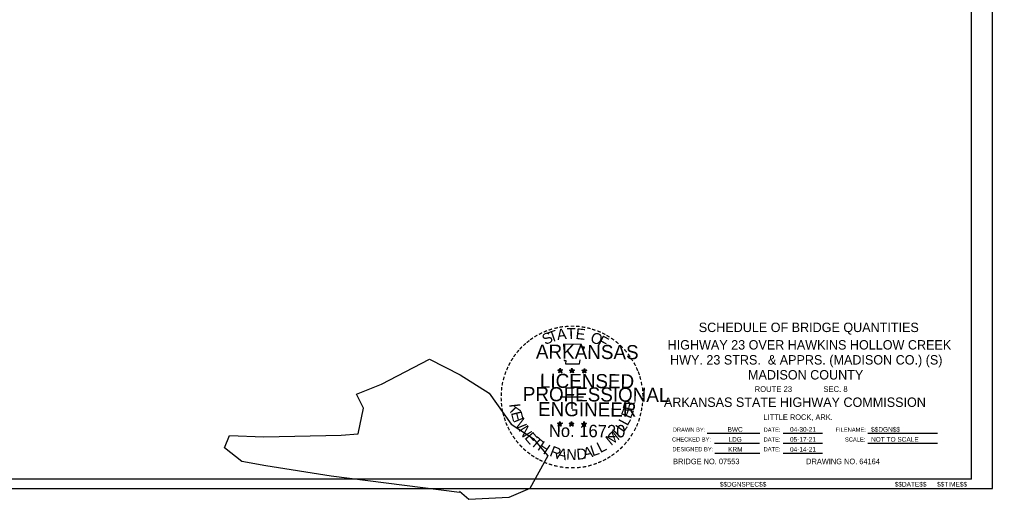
# Model space of a CAD drawing. Extents: x -1.3 to 32.1, y -0.4 to 20.7.
# Drawn here: x 11.36 to 32.07, y -0.43 to 9.78 of the extents above; entities that cross this region are included whole.
import ezdxf

# ---------------------------------------------------------------- set-up
doc = ezdxf.new("R2010")
doc.units = 0
for name, color, linetype in [('49B', 7, 'Continuous'), ('Level 1', 7, 'Continuous'), ('Level 4', 7, 'Continuous'), ('Level 48', 7, 'Continuous'), ('Level 63', 7, 'Continuous'), ('R_No Plot', 7, 'Continuous'), ('S_TREE', 7, 'Continuous')]:
    doc.layers.add(name, color=color, linetype=linetype)

msp = doc.modelspace()

# ---------------------------------------------------------------- linework, layer by layer
at = {"layer": '49B'}
for p, q in [((22.816, 2.325), (22.87, 2.308)), ((22.816, 2.325), (22.855, 2.323)), ((22.816, 2.325), (22.855, 2.321)), ((22.816, 2.325), (22.851, 2.315)), ((22.816, 2.325), (22.851, 2.31)), ((22.816, 2.325), (22.851, 2.308)), ((22.816, 2.325), (22.851, 2.302)), ((22.838, 2.263), (22.87, 2.308)), ((22.838, 2.263), (22.851, 2.306)), ((22.838, 2.263), (22.855, 2.3)), ((22.838, 2.263), (22.857, 2.299)), ((22.838, 2.263), (22.862, 2.295)), ((22.838, 2.263), (22.87, 2.295)), ((22.838, 2.263), (22.87, 2.291)), ((22.87, 2.365), (22.862, 2.325)), ((22.87, 2.365), (22.862, 2.328)), ((22.87, 2.365), (22.866, 2.328)), ((22.87, 2.308), (22.87, 2.365)), ((22.87, 2.365), (22.879, 2.325)), ((22.87, 2.365), (22.877, 2.328)), ((22.87, 2.365), (22.872, 2.328)), ((22.921, 2.325), (22.87, 2.308)), ((22.901, 2.262), (22.87, 2.308)), ((22.901, 2.262), (22.87, 2.295)), ((22.901, 2.262), (22.87, 2.291)), ((22.921, 2.325), (22.873, 2.321)), ((22.901, 2.262), (22.873, 2.295)), ((22.921, 2.325), (22.879, 2.317)), ((22.921, 2.325), (22.879, 2.313)), ((22.901, 2.262), (22.879, 2.306)), ((22.901, 2.262), (22.879, 2.3)), ((22.901, 2.262), (22.884, 2.308)), ((22.921, 2.325), (22.886, 2.313)), ((22.921, 2.325), (22.892, 2.31)), ((22.921, 2.325), (22.894, 2.308)), ((23.066, 2.323), (23.119, 2.308)), ((23.066, 2.323), (23.105, 2.321)), ((23.066, 2.323), (23.105, 2.317)), ((23.066, 2.323), (23.105, 2.315)), ((23.066, 2.323), (23.103, 2.308)), ((23.066, 2.323), (23.103, 2.306)), ((23.066, 2.323), (23.103, 2.3)), ((23.088, 2.262), (23.119, 2.308)), ((23.088, 2.262), (23.105, 2.302)), ((23.088, 2.262), (23.105, 2.3)), ((23.088, 2.262), (23.106, 2.299)), ((23.088, 2.262), (23.112, 2.293)), ((23.088, 2.262), (23.119, 2.293)), ((23.088, 2.262), (23.119, 2.291)), ((23.119, 2.362), (23.112, 2.323)), ((23.119, 2.362), (23.112, 2.325)), ((23.119, 2.362), (23.114, 2.325)), ((23.119, 2.308), (23.119, 2.362)), ((23.119, 2.362), (23.129, 2.323)), ((23.119, 2.362), (23.127, 2.325)), ((23.119, 2.362), (23.121, 2.325)), ((23.171, 2.323), (23.119, 2.308)), ((23.151, 2.262), (23.119, 2.308)), ((23.151, 2.262), (23.119, 2.293)), ((23.151, 2.262), (23.119, 2.291)), ((23.171, 2.323), (23.125, 2.321)), ((23.151, 2.262), (23.125, 2.293)), ((23.171, 2.323), (23.129, 2.315)), ((23.171, 2.323), (23.129, 2.313)), ((23.151, 2.262), (23.129, 2.306)), ((23.151, 2.262), (23.129, 2.299)), ((23.151, 2.262), (23.134, 2.306)), ((23.171, 2.323), (23.136, 2.31)), ((23.171, 2.323), (23.142, 2.308)), ((23.171, 2.323), (23.143, 2.306)), ((23.33, 2.321), (23.384, 2.302)), ((23.33, 2.321), (23.373, 2.315)), ((23.33, 2.321), (23.369, 2.313)), ((23.33, 2.321), (23.369, 2.31)), ((23.33, 2.321), (23.367, 2.306)), ((23.33, 2.321), (23.367, 2.3)), ((23.33, 2.321), (23.367, 2.3)), ((23.351, 2.26), (23.384, 2.302)), ((23.351, 2.26), (23.369, 2.3)), ((23.351, 2.26), (23.373, 2.295)), ((23.351, 2.26), (23.373, 2.293)), ((23.351, 2.26), (23.384, 2.293)), ((23.351, 2.26), (23.38, 2.291)), ((23.351, 2.26), (23.388, 2.286)), ((23.384, 2.358), (23.375, 2.323)), ((23.384, 2.358), (23.38, 2.321)), ((23.384, 2.358), (23.38, 2.321)), ((23.384, 2.302), (23.384, 2.358)), ((23.384, 2.358), (23.395, 2.321)), ((23.384, 2.358), (23.391, 2.321)), ((23.384, 2.358), (23.388, 2.321)), ((23.436, 2.321), (23.384, 2.302)), ((23.414, 2.26), (23.384, 2.302)), ((23.414, 2.26), (23.384, 2.293)), ((23.414, 2.26), (23.384, 2.286)), ((23.436, 2.321), (23.39, 2.315)), ((23.414, 2.26), (23.39, 2.291)), ((23.436, 2.321), (23.395, 2.313)), ((23.436, 2.321), (23.395, 2.308)), ((23.414, 2.26), (23.395, 2.3)), ((23.414, 2.26), (23.395, 2.295)), ((23.414, 2.26), (23.399, 2.3)), ((23.436, 2.321), (23.402, 2.306)), ((23.436, 2.321), (23.404, 2.306)), ((23.436, 2.321), (23.41, 2.302)), ((22.809, 1.189), (22.862, 1.172)), ((22.809, 1.189), (22.847, 1.187)), ((22.809, 1.189), (22.846, 1.181)), ((22.809, 1.189), (22.846, 1.181)), ((22.809, 1.189), (22.846, 1.174)), ((22.809, 1.189), (22.846, 1.172)), ((22.809, 1.189), (22.846, 1.17)), ((22.827, 1.131), (22.862, 1.172)), ((22.827, 1.131), (22.846, 1.172)), ((22.827, 1.131), (22.847, 1.165)), ((22.827, 1.131), (22.849, 1.165)), ((22.827, 1.131), (22.862, 1.163)), ((22.827, 1.131), (22.855, 1.159)), ((22.827, 1.131), (22.862, 1.157)), ((22.862, 1.229), (22.851, 1.192)), ((22.862, 1.229), (22.855, 1.189)), ((22.862, 1.229), (22.857, 1.189)), ((22.892, 1.128), (22.859, 1.157)), ((22.862, 1.172), (22.862, 1.229)), ((22.862, 1.229), (22.87, 1.189)), ((22.862, 1.229), (22.87, 1.189)), ((22.862, 1.229), (22.862, 1.189)), ((22.914, 1.189), (22.862, 1.172)), ((22.892, 1.128), (22.862, 1.172)), ((22.892, 1.128), (22.862, 1.159)), ((22.892, 1.128), (22.864, 1.159)), ((22.914, 1.189), (22.866, 1.187)), ((22.914, 1.189), (22.87, 1.181)), ((22.914, 1.189), (22.87, 1.179)), ((22.892, 1.128), (22.87, 1.172)), ((22.892, 1.128), (22.87, 1.165)), ((22.914, 1.189), (22.877, 1.178)), ((22.892, 1.128), (22.877, 1.172)), ((22.914, 1.189), (22.881, 1.174)), ((22.914, 1.189), (22.884, 1.172)), ((23.058, 1.189), (23.112, 1.172)), ((23.058, 1.189), (23.097, 1.185)), ((23.058, 1.189), (23.097, 1.181)), ((23.058, 1.189), (23.097, 1.179)), ((23.058, 1.189), (23.095, 1.174)), ((23.058, 1.189), (23.095, 1.17)), ((23.058, 1.189), (23.095, 1.166)), ((23.077, 1.128), (23.112, 1.172)), ((23.077, 1.128), (23.097, 1.17)), ((23.077, 1.128), (23.097, 1.163)), ((23.077, 1.128), (23.099, 1.163)), ((23.077, 1.128), (23.105, 1.159)), ((23.077, 1.128), (23.112, 1.159)), ((23.077, 1.128), (23.112, 1.155)), ((23.112, 1.226), (23.103, 1.189)), ((23.112, 1.226), (23.105, 1.189)), ((23.112, 1.226), (23.106, 1.189)), ((23.142, 1.128), (23.11, 1.155)), ((23.112, 1.172), (23.112, 1.226)), ((23.112, 1.226), (23.119, 1.187)), ((23.112, 1.226), (23.119, 1.187)), ((23.112, 1.226), (23.112, 1.189)), ((23.162, 1.187), (23.112, 1.172)), ((23.142, 1.128), (23.112, 1.172)), ((23.142, 1.128), (23.112, 1.159)), ((23.142, 1.128), (23.114, 1.159)), ((23.162, 1.187), (23.118, 1.187)), ((23.162, 1.187), (23.119, 1.179)), ((23.162, 1.187), (23.119, 1.179)), ((23.142, 1.128), (23.119, 1.17)), ((23.142, 1.128), (23.119, 1.165)), ((23.162, 1.187), (23.127, 1.174)), ((23.142, 1.128), (23.127, 1.17)), ((23.162, 1.187), (23.132, 1.172)), ((23.162, 1.187), (23.134, 1.17)), ((23.323, 1.185), (23.377, 1.166)), ((23.323, 1.185), (23.362, 1.181)), ((23.323, 1.185), (23.362, 1.178)), ((23.323, 1.185), (23.36, 1.174)), ((23.323, 1.185), (23.36, 1.17)), ((23.323, 1.185), (23.358, 1.166)), ((23.323, 1.185), (23.358, 1.163)), ((23.343, 1.124), (23.377, 1.166)), ((23.343, 1.124), (23.36, 1.166)), ((23.343, 1.124), (23.362, 1.159)), ((23.343, 1.124), (23.365, 1.159)), ((23.343, 1.124), (23.369, 1.155)), ((23.343, 1.124), (23.375, 1.155)), ((23.343, 1.124), (23.377, 1.152)), ((23.377, 1.224), (23.367, 1.185)), ((23.377, 1.224), (23.369, 1.185)), ((23.377, 1.224), (23.373, 1.185)), ((23.406, 1.124), (23.375, 1.155)), ((23.406, 1.124), (23.375, 1.152)), ((23.377, 1.166), (23.377, 1.224)), ((23.377, 1.224), (23.384, 1.185)), ((23.377, 1.224), (23.384, 1.185)), ((23.377, 1.224), (23.377, 1.185)), ((23.428, 1.185), (23.377, 1.166)), ((23.406, 1.124), (23.377, 1.166)), ((23.406, 1.124), (23.38, 1.155)), ((23.428, 1.185), (23.382, 1.181)), ((23.428, 1.185), (23.384, 1.178)), ((23.428, 1.185), (23.384, 1.174)), ((23.406, 1.124), (23.384, 1.159)), ((23.406, 1.124), (23.388, 1.166)), ((23.406, 1.124), (23.39, 1.166)), ((23.428, 1.185), (23.395, 1.172)), ((23.428, 1.185), (23.397, 1.166)), ((23.428, 1.185), (23.399, 1.166))]:
    msp.add_line(p, q, dxfattribs=at)
for points in [[(22.938, 2.872), (22.944, 2.757)], [(23.364, 2.757), (23.388, 2.809), (23.317, 2.809), (23.321, 2.868), (22.938, 2.872)], [(22.951, 2.543), (22.953, 2.528), (22.986, 2.526), (22.981, 2.458), (23.282, 2.456), (23.29, 2.543)], [(22.87, 2.365), (22.901, 2.262), (22.816, 2.325), (22.921, 2.325), (22.838, 2.263), (22.87, 2.365)], [(23.119, 2.362), (23.151, 2.262), (23.066, 2.323), (23.171, 2.323), (23.088, 2.262), (23.119, 2.362)], [(23.384, 2.358), (23.414, 2.26), (23.33, 2.321), (23.436, 2.321), (23.351, 2.26), (23.384, 2.358)], [(22.862, 1.229), (22.892, 1.128), (22.809, 1.189), (22.914, 1.189), (22.827, 1.131), (22.862, 1.229)], [(23.112, 1.226), (23.142, 1.128), (23.058, 1.189), (23.162, 1.187), (23.077, 1.128), (23.112, 1.226)], [(23.377, 1.224), (23.406, 1.124), (23.323, 1.185), (23.428, 1.185), (23.343, 1.124), (23.377, 1.224)]]:
    msp.add_lwpolyline(points, dxfattribs=at)
for centre, radius in [((22.869, 2.308), 0.0258), ((22.869, 2.308), 0.0234), ((22.869, 2.308), 0.0217), ((22.869, 2.308), 0.0199), ((22.869, 2.308), 0.0173), ((22.869, 2.308), 0.0161), ((22.869, 2.308), 0.0149), ((22.869, 2.308), 0.0128), ((22.869, 2.308), 0.0112), ((22.869, 2.308), 0.00931), ((22.869, 2.308), 0.00743), ((22.869, 2.308), 0.00554), ((22.869, 2.308), 0.00444), ((22.869, 2.308), 0.00216), ((23.119, 2.306), 0.0258), ((23.119, 2.306), 0.0234), ((23.119, 2.306), 0.0217), ((23.119, 2.306), 0.0199), ((23.119, 2.306), 0.0173), ((23.119, 2.306), 0.0161), ((23.119, 2.306), 0.0149), ((23.119, 2.306), 0.0128), ((23.119, 2.306), 0.0112), ((23.119, 2.306), 0.00931), ((23.119, 2.306), 0.00743), ((23.119, 2.306), 0.00554), ((23.119, 2.306), 0.00444), ((23.119, 2.306), 0.00216), ((23.384, 2.303), 0.0258), ((23.384, 2.303), 0.0234), ((23.384, 2.303), 0.0217), ((23.384, 2.303), 0.0199), ((23.384, 2.303), 0.0173), ((23.384, 2.303), 0.0161), ((23.384, 2.303), 0.0149), ((23.384, 2.303), 0.0128), ((23.384, 2.303), 0.0112), ((23.384, 2.303), 0.00931), ((23.384, 2.303), 0.00743), ((23.384, 2.303), 0.00554), ((23.384, 2.303), 0.00444), ((23.384, 2.303), 0.00216), ((22.86, 1.173), 0.0258), ((22.86, 1.173), 0.0234), ((22.86, 1.173), 0.0217), ((22.86, 1.173), 0.0199), ((22.86, 1.173), 0.0173), ((22.86, 1.173), 0.0161), ((22.86, 1.173), 0.0149), ((22.86, 1.173), 0.0128), ((22.86, 1.173), 0.0112), ((22.86, 1.173), 0.00931), ((22.86, 1.173), 0.00743), ((22.86, 1.173), 0.00554), ((22.86, 1.173), 0.00444), ((22.86, 1.173), 0.00216), ((23.11, 1.171), 0.0258), ((23.11, 1.171), 0.0234), ((23.11, 1.171), 0.0217), ((23.11, 1.171), 0.0199), ((23.11, 1.171), 0.0173), ((23.11, 1.171), 0.0161), ((23.11, 1.171), 0.0149), ((23.11, 1.171), 0.0128), ((23.11, 1.171), 0.0112), ((23.11, 1.171), 0.00931), ((23.11, 1.171), 0.00743), ((23.11, 1.171), 0.00554), ((23.11, 1.171), 0.00444), ((23.11, 1.171), 0.00216), ((23.375, 1.168), 0.0258), ((23.375, 1.168), 0.0234), ((23.375, 1.168), 0.0217), ((23.375, 1.168), 0.0199), ((23.375, 1.168), 0.0173), ((23.375, 1.168), 0.0161), ((23.375, 1.168), 0.0149), ((23.375, 1.168), 0.0128), ((23.375, 1.168), 0.0112), ((23.375, 1.168), 0.00931), ((23.375, 1.168), 0.00743), ((23.375, 1.168), 0.00554), ((23.375, 1.168), 0.00444), ((23.375, 1.168), 0.00216)]:
    msp.add_circle(centre, radius, dxfattribs=at)
at = {"layer": 'Level 1'}
for q in [(31.617, 20.545), (-0.001, -0.001)]:
    msp.add_line((31.617, -0.001), q, dxfattribs=at)
at = {"layer": 'Level 4'}
for p, q in [((25.996, 0.976), (27.116, 0.976)), ((27.612, 0.976), (28.446, 0.976)), ((29.416, 0.976), (30.894, 0.976)), ((26.154, 0.764), (27.107, 0.764)), ((27.612, 0.764), (28.446, 0.764)), ((29.416, 0.764), (30.894, 0.764)), ((26.161, 0.552), (27.113, 0.552)), ((27.612, 0.552), (28.446, 0.552)), ((19.866, -0.001), (-0.001, -0.001))]:
    msp.add_line(p, q, dxfattribs=at)
at = {"layer": 'Level 63'}
msp.add_lwpolyline([(-1.263, -0.201), (32.067, -0.201), (32.067, 20.747), (-1.263, 20.747)], close=True, dxfattribs=at)
at = {"layer": 'R_No Plot'}
for p, q in [((23.116, 1.999), (23.116, 1.499)), ((22.866, 1.749), (23.366, 1.749))]:
    msp.add_line(p, q, dxfattribs=at)
at = {"layer": 'S_TREE'}
msp.add_lwpolyline([(20.724, -0.281), (17.993, 0.063), (16.605, 0.281), (16.096, 0.374), (15.723, 0.666), (15.831, 0.926), (16.565, 0.898), (18.21, 0.933), (18.573, 0.964), (18.684, 1.511), (18.537, 1.812), (19.067, 2.021), (20.088, 2.557), (20.737, 2.22), (21.357, 1.833), (21.822, 1.172), (22.291, 0.868), (22.607, 0.493), (22.225, -0.199), (21.775, -0.39), (20.927, -0.434), (20.724, -0.264)], dxfattribs=at)

# ---------------------------------------------------------------- texts
at = {"layer": '49B'}
for s, height, rotation, p in [('-', 0.24, 28.3942, (22.448, 2.992)), ('S', 0.231, 25.7249, (22.551, 2.85)), ('-', 0.24, 23.9096, (22.542, 3.039)), ('T', 0.231, 19.3365, (22.666, 2.902)), ('-', 0.24, 18.7785, (22.638, 3.079)), ('-', 0.24, 13.2325, (22.751, 3.114)), ('A', 0.231, 6.5597, (22.809, 2.959)), ('-', 0.24, 9.8217, (22.851, 3.139)), ('-', 0.24, 5.4992, (22.962, 3.153)), ('T', 0.231, 0.1713, (23.008, 2.985)), ('-', 0.24, 359.7886, (23.077, 3.164)), ('-', 0.24, 357.3454, (23.188, 3.161)), ('E', 0.231, 353.7829, (23.188, 2.985)), ('-', 0.24, 351.7641, (23.297, 3.151)), ('-', 0.24, 346.8073, (23.406, 3.135)), ('O', 0.231, 338.7567, (23.491, 2.929)), ('-', 0.24, 341.9386, (23.501, 3.109)), ('-', 0.24, 337.4575, (23.61, 3.076)), ('-', 0.24, 333.7235, (23.706, 3.037)), ('-', 0.24, 42.5646, (22.133, 2.761)), ('-', 0.24, 38.5531, (22.2, 2.822)), ('-', 0.24, 35.8341, (22.27, 2.88)), ('-', 0.24, 33.666, (22.357, 2.939)), ('F', 0.231, 332.3683, (23.65, 2.865)), ('-', 0.24, 329.2433, (23.791, 2.992)), ('-', 0.24, 325.4651, (23.887, 2.935)), ('-', 0.24, 320.1321, (23.978, 2.872)), ('-', 0.24, 50.2166, (22.004, 2.619)), ('-', 0.24, 48.0254, (22.065, 2.691)), ('ARKANSAS', 0.2998, 359.6024, (22.352, 2.567)), ('-', 0.24, 315.181, (24.068, 2.798)), ('-', 0.24, 309.4821, (24.152, 2.715)), ('-', 0.24, 62.4738, (21.847, 2.362)), ('-', 0.24, 57.673, (21.893, 2.452)), ('-', 0.24, 53.8349, (21.941, 2.534)), ('-', 0.24, 306.2546, (24.228, 2.624)), ('-', 0.21, 303.2777, (24.302, 2.537)), ('-', 0.24, 299.2708, (24.348, 2.447)), ('-', 0.24, 71.9969, (21.773, 2.177)), ('-', 0.24, 67.3767, (21.808, 2.271)), ('-', 0.24, 294.2652, (24.396, 2.354)), ('-', 0.24, 290.1752, (24.437, 2.271)), ('-', 0.24, 80.8037, (21.721, 1.964)), ('-', 0.24, 75.0634, (21.743, 2.069)), ('LICENSED', 0.2998, 359.6024, (22.436, 1.946)), ('-', 0.24, 284.7257, (24.468, 2.182)), ('-', 0.24, 280.1517, (24.498, 2.069)), ('-', 0.24, 84.7887, (21.71, 1.86)), ('PROFESSIONAL', 0.29977, 359.6024, (22.072, 1.664)), ('-', 0.24, 276.1986, (24.524, 1.955)), ('-', 0.24, 93.7983, (21.71, 1.646)), ('-', 0.24, 88.6646, (21.706, 1.755)), ('R', 0.231, 76.435, (24.419, 1.436)), ('-', 0.24, 273.9325, (24.531, 1.845)), ('-', 0.24, 269.5431, (24.535, 1.753)), ('-', 0.24, 98.5503, (21.721, 1.544)), ('-', 0.24, 101.3173, (21.737, 1.435)), ('K', 0.231, 276.5164, (21.784, 1.595)), ('ENGINEER', 0.2998, 359.6024, (22.396, 1.344)), ('E', 0.231, 68.7273, (24.369, 1.273)), ('-', 0.24, 260.5977, (24.518, 1.555)), ('-', 0.24, 263.1196, (24.531, 1.653)), ('-', 0.24, 105.0602, (21.763, 1.346)), ('-', 0.24, 108.6898, (21.795, 1.253)), ('E', 0.231, 284.0484, (21.818, 1.413)), ('N', 0.231, 292.1008, (21.871, 1.253)), ('L', 0.231, 61.5663, (24.3, 1.12)), ('-', 0.24, 252.4705, (24.475, 1.344)), ('-', 0.24, 255.365, (24.501, 1.453)), ('-', 0.24, 113.6667, (21.832, 1.161)), ('-', 0.24, 115.3313, (21.878, 1.068)), ('N', 0.231, 301.7076, (21.971, 1.052)), ('No. 16720', 0.2638, 359.6024, (22.627, 0.9)), ('I', 0.231, 46.8246, (24.123, 0.864)), ('L', 0.231, 54.4731, (24.213, 0.979)), ('-', 0.24, 244.2221, (24.4, 1.15)), ('-', 0.24, 247.4911, (24.442, 1.242)), ('-', 0.24, 120.0495, (21.93, 0.98)), ('-', 0.24, 125.4958, (21.991, 0.896)), ('-', 0.24, 130.3205, (22.058, 0.813)), ('E', 0.231, 310.1399, (22.098, 0.877)), ('T', 0.231, 318.2142, (22.224, 0.748)), ('M', 0.231, 39.2604, (23.952, 0.701)), ('-', 0.24, 233.4476, (24.283, 0.941)), ('-', 0.24, 238.6736, (24.34, 1.039)), ('-', 0.24, 133.8262, (22.135, 0.732)), ('-', 0.24, 138.5362, (22.211, 0.661)), ('H', 0.231, 326.2077, (22.369, 0.636)), ('R', 0.231, 338.5035, (22.626, 0.501)), ('A', 0.231, 346.2417, (22.788, 0.449)), ('N', 0.231, 357.4327, (22.993, 0.415)), ('D', 0.231, 4.1496, (23.222, 0.413)), ('A', 0.231, 11.6808, (23.378, 0.435)), ('L', 0.231, 18.7412, (23.557, 0.483)), ('L', 0.231, 26.3818, (23.721, 0.553)), ('-', 0.24, 220.6875, (24.065, 0.697)), ('-', 0.24, 225.3677, (24.142, 0.772)), ('-', 0.24, 233.4476, (24.213, 0.859)), ('-', 0.24, 144.2487, (22.298, 0.6)), ('-', 0.24, 147.6922, (22.379, 0.543)), ('-', 0.24, 151.1728, (22.465, 0.495)), ('-', 0.24, 154.2026, (22.546, 0.456)), ('-', 0.24, 206.9592, (23.817, 0.517)), ('-', 0.24, 211.8515, (23.9, 0.569)), ('-', 0.24, 215.3387, (23.98, 0.626)), ('-', 0.24, 158.1636, (22.638, 0.415)), ('-', 0.24, 162.4007, (22.742, 0.384)), ('-', 0.24, 167.1579, (22.847, 0.36)), ('-', 0.24, 172.7179, (22.962, 0.343)), ('-', 0.24, 176.1207, (23.075, 0.332)), ('-', 0.24, 181.1942, (23.186, 0.336)), ('-', 0.24, 185.4191, (23.308, 0.345)), ('-', 0.24, 190.8882, (23.419, 0.364)), ('-', 0.24, 195.0767, (23.528, 0.393)), ('-', 0.24, 200.3208, (23.63, 0.43)), ('-', 0.24, 203.854, (23.723, 0.471))]:
    msp.add_text(s, height=height, rotation=rotation, dxfattribs=at).set_placement(p)
at = {"layer": 'Level 4'}
for s, height, rotation, p in [('SCHEDULE OF BRIDGE QUANTITIES', 0.2, 359.9982, (25.817, 3.131)), ('HIGHWAY 23 OVER HAWKINS HOLLOW CREEK', 0.2, 359.9982, (25.154, 2.759)), ('HWY. 23 STRS.  & APPRS. (MADISON CO.) (S)', 0.2, 359.9982, (25.206, 2.44)), ('MADISON COUNTY', 0.2, 359.9982, (26.865, 2.121)), ('ROUTE 23', 0.1219, 360, (27.005, 1.856)), ('SEC. 8', 0.1219, 360, (28.468, 1.856)), ('BWC', 0.1, 0.0001, (26.43, 1.009)), ('04-30-21', 0.1, 0.0001, (27.758, 1.009)), ('$$DGN$$', 0.1, 0.0001, (29.483, 1.009)), ('LDG', 0.1, 0.0001, (26.449, 0.797)), ('05-17-21', 0.1, 0.0001, (27.758, 0.797)), ('NOT TO SCALE', 0.1, 0.0001, (29.483, 0.797)), ('KRM', 0.1, 0.0001, (26.442, 0.585)), ('04-14-21', 0.1, 0.0001, (27.758, 0.585))]:
    msp.add_text(s, height=height, rotation=rotation, dxfattribs=at).set_placement(p)
for s, height, p in [('ARKANSAS STATE HIGHWAY COMMISSION', 0.2, (25.076, 1.538)), ('LITTLE ROCK, ARK.', 0.11808, (27.194, 1.261)), ('DRAWN BY:', 0.0886, (25.263, 1.009)), ('DATE:', 0.0886, (27.196, 1.009)), ('FILENAME:', 0.0886, (28.726, 1.009)), ('CHECKED BY:', 0.08856, (25.248, 0.801)), ('DATE:', 0.0886, (27.196, 0.801)), ('SCALE:', 0.0886, (28.927, 0.801)), ('DESIGNED BY:', 0.08856, (25.256, 0.593)), ('DATE:', 0.0886, (27.196, 0.593)), ('BRIDGE NO. 07553', 0.11808, (25.271, 0.319)), ('DRAWING NO. 64164', 0.11808, (28.101, 0.319))]:
    msp.add_text(s, height=height, dxfattribs=at).set_placement(p)
at = {"layer": 'Level 48'}
for s, p in [('$$DGNSPEC$$', (26.264, -0.159)), ('$$DATE$$', (29.986, -0.159)), ('$$TIME$$', (30.887, -0.159))]:
    msp.add_text(s, height=0.1, dxfattribs=at).set_placement(p)

doc.saveas('drawing.dxf')
